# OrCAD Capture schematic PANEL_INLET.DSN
size A
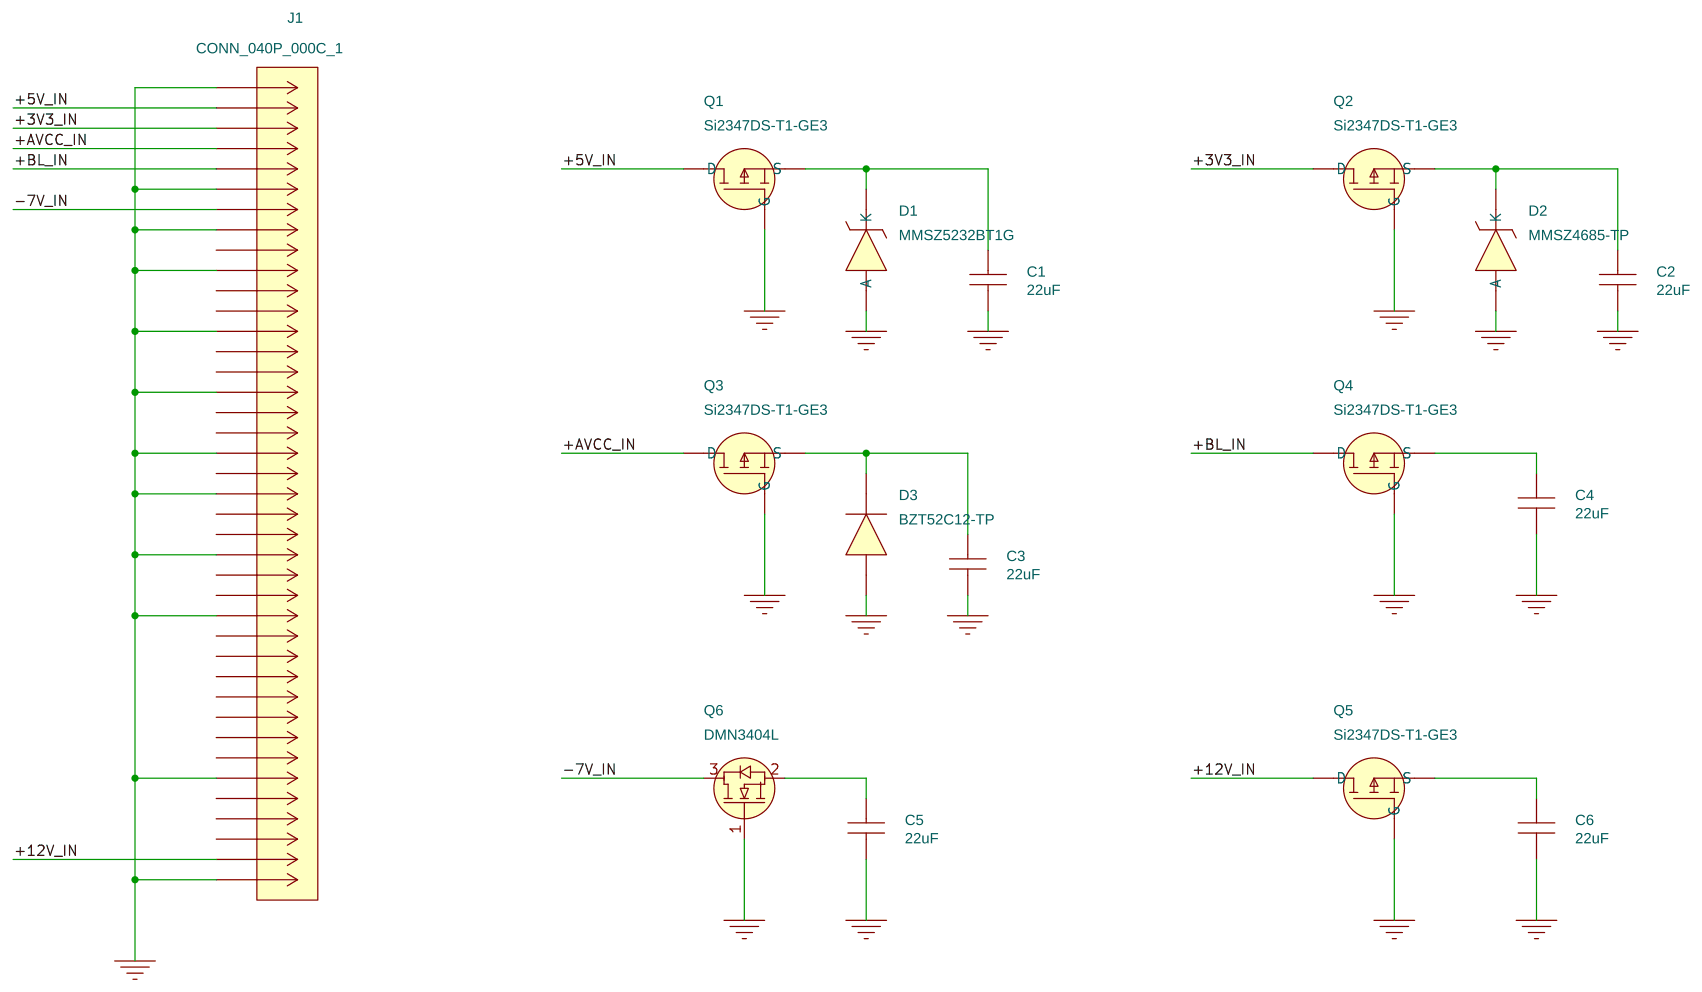
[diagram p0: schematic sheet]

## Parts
C1  22uF
C2  22uF
C3  22uF
C4  22uF
C5  22uF
C6  22uF
D1  MMSZ5232BT1G  [SOD3716X135N]
D2  MMSZ4685-TP  [SOD3716X135N]
D3  BZT52C12-TP  [SOD3716X135N]
J1  CONN_040P_000C_1  [CONN_FH12-40S-0P5SH_55__HIR]
Q1  Si2347DS-T1-GE3  [SOT95P237X112-3N]
Q2  Si2347DS-T1-GE3  [SOT95P237X112-3N]
Q3  Si2347DS-T1-GE3  [SOT95P237X112-3N]
Q4  Si2347DS-T1-GE3  [SOT95P237X112-3N]
Q5  Si2347DS-T1-GE3  [SOT95P237X112-3N]
Q6  DMN3404L  [SOT23_DIO]

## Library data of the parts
C1-C6 = CAP_NP
D1 = MMSZ5232BT1G: Manufacturer Name: onsemi
D2 = MMSZ4685-TP: Manufacturer Name: MCC
D3 = BZT52C12-TP: Manufacturer Name: MCC
J1 = FH12-40S-0P5SH55: Manufacturer Name: Hirose; Manufacturer Part Number: FH12-40S-0.5SH(55); Part Number: FH12-40S-0.5SH(55)
Q1-Q5 = Si2347DS-T1-GE3: Manufacturer Name: Vishay
Q6 = DMN3404L-7: Manufacturer Name: Diodes Inc

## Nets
+3V3_IN: J1.3 Q2.3(D)
+5V_IN: J1.2 Q1.3(D)
+12V_IN: J1.39 Q5.3(D)
+AVCC_IN: J1.4 Q3.3(D)
-7V_IN: J1.7 Q6.3
GND: C1.2 C2.2 C3.2 C4.2 C5.2 C6.2 D1.2(A) D2.2(A) D3.2(A) J1.1 J1.6 J1.8 J1.10 J1.13 J1.16 J1.19 J1.21 J1.24 J1.27 J1.35 J1.40 Q1.1(G) Q2.1(G) Q3.1(G) Q4.1(G) Q5.1(G) Q6.1
+BL_IN: J1.5 Q4.3(D)
N03746: C1.1 D1.1(K) Q1.2(S)
N04158: C2.1 D2.1(K) Q2.2(S)
N04259: C3.1 D3.1(K) Q3.2(S)
N04422: C4.1 Q4.2(S)
N04509: C5.1 Q6.2
N04599: C6.1 Q5.2(S)

Not connected (* = marked no-connect by the designer): J1 9 11 12 14 15 17 18 20 22 23 25 26 28 29 30 31 32 33 34 36 37 38
